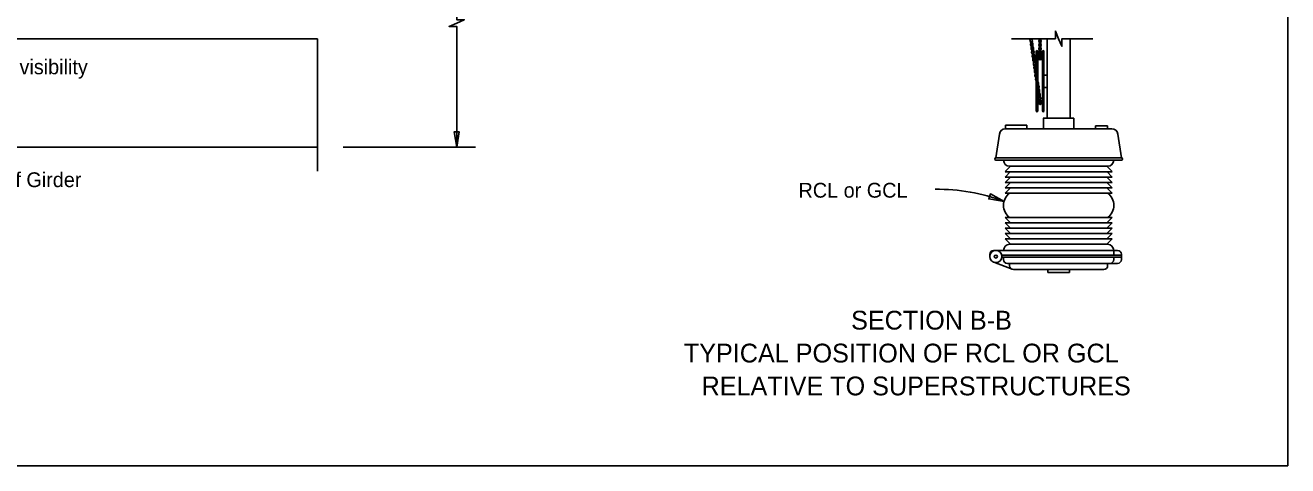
# Model space of a CAD drawing. Extents: x 0 to 20.5, y 0 to 13.
# Drawn here: x 11.94 to 20.53, y 0 to 3 of the extents above; entities that cross this region are included whole.
import ezdxf

# ---------------------------------------------------------------- set-up
doc = ezdxf.new("R2010")
doc.units = 0
for name, color, linetype in [('ActivePts-ConstElements', 7, 'Continuous'), ('Dimension', 7, 'Continuous'), ('Miscellaneous', 7, 'Continuous'), ('Miscellaneous1', 7, 'Continuous'), ('NavLight', 7, 'Continuous'), ('SupstrConc', 7, 'Continuous'), ('TextStructures', 7, 'Continuous')]:
    doc.layers.add(name, color=color, linetype=linetype)

msp = doc.modelspace()

# ---------------------------------------------------------------- linework, layer by layer
at = {"layer": 'ActivePts-ConstElements'}
msp.add_lwpolyline([(0, 0), (20.5253, 0), (20.5253, 12.9731), (0, 12.9731)], close=True, dxfattribs=at)
at = {"layer": 'Dimension'}
msp.add_line((14.0993, 2.1697), (14.9992, 2.1697), dxfattribs=at)
for points in [[(14.8718, 2.1697), (14.8718, 2.9926), (14.8202, 2.9926), (14.8718, 3.0151), (14.9235, 3.0376), (14.8718, 3.0376), (14.8718, 4.7665)], [(5.858, 2.9088), (10.1884, 2.9088), (10.1884, 2.9604), (10.2109, 2.9088), (10.2334, 2.8571), (10.2334, 2.9088), (13.9245, 2.9088)], [(18.6451, 2.9088), (18.9443, 2.9088), (18.9443, 2.9605), (18.9668, 2.9088), (18.9893, 2.8572), (18.9893, 2.9088), (19.2004, 2.9088)], [(13.9245, 2.0075), (13.9245, 2.9088)]]:
    msp.add_lwpolyline(points, dxfattribs=at)
for points in [[(14.8718, 2.1697), (14.8895, 2.2738), (14.8542, 2.2738)], [(18.5953, 1.801), (18.5023, 1.8511), (18.491, 1.8177)]]:
    msp.add_lwpolyline(points, close=True, dxfattribs=at)
msp.add_arc((18.1425, 0.5937), 1.2893, 69.44292, 90.68885, dxfattribs=at)
at = {"layer": 'Miscellaneous'}
for p, q in [((18.8149, 2.8221), (18.8149, 2.4156)), ((18.8253, 2.8221), (18.8253, 2.4156)), ((18.8409, 2.8273), (18.8409, 2.7649)), ((18.8565, 2.8221), (18.8565, 2.4156)), ((18.8669, 2.8221), (18.8669, 2.4156)), ((18.8877, 2.6606), (18.8669, 2.6606)), ((18.8877, 2.5772), (18.8669, 2.5772)), ((18.6386, 2.0396), (18.6021, 2.0031)), ((18.6386, 2.0031), (18.6021, 1.9667)), ((18.9668, 2.003), (18.6022, 2.003)), ((18.9667, 2.003), (19.3314, 2.003)), ((19.2949, 2.0396), (19.3313, 2.0031)), ((19.2949, 2.0031), (19.3313, 1.9667)), ((18.6386, 1.9667), (18.6021, 1.9302)), ((18.6386, 1.9302), (18.6021, 1.8938)), ((18.6386, 1.8938), (18.6021, 1.8573)), ((18.9668, 1.9666), (18.6022, 1.9666)), ((18.9668, 1.9301), (18.6022, 1.9301)), ((18.9668, 1.8937), (18.6022, 1.8937)), ((18.9667, 1.9666), (19.3314, 1.9666)), ((18.9667, 1.9301), (19.3314, 1.9301)), ((18.9667, 1.8937), (19.3314, 1.8937)), ((19.2949, 1.9667), (19.3313, 1.9302)), ((19.2949, 1.9302), (19.3313, 1.8938)), ((19.2949, 1.8938), (19.3313, 1.8573)), ((18.9668, 1.8572), (18.6022, 1.8572)), ((18.9667, 1.8572), (19.3314, 1.8572)), ((18.6386, 1.6542), (18.6021, 1.6906)), ((18.6386, 1.6177), (18.6021, 1.6542)), ((18.9668, 1.6905), (18.6022, 1.6905)), ((18.9668, 1.6541), (18.6022, 1.6541)), ((18.9667, 1.6905), (19.3314, 1.6905)), ((18.9667, 1.6541), (19.3314, 1.6541)), ((19.2949, 1.6542), (19.3313, 1.6906)), ((19.2949, 1.6177), (19.3313, 1.6542)), ((18.6386, 1.5813), (18.6021, 1.6177)), ((18.6386, 1.5448), (18.6021, 1.5813)), ((18.9668, 1.6176), (18.6022, 1.6176)), ((18.9668, 1.5812), (18.6022, 1.5812)), ((18.9667, 1.6176), (19.3314, 1.6176)), ((18.9667, 1.5812), (19.3314, 1.5812)), ((19.2949, 1.5813), (19.3313, 1.6177)), ((19.2949, 1.5448), (19.3313, 1.5813)), ((18.6386, 1.5083), (18.6021, 1.5448)), ((18.9668, 1.5447), (18.6022, 1.5447)), ((18.9667, 1.5447), (19.3314, 1.5447)), ((19.2949, 1.5083), (19.3313, 1.5448))]:
    msp.add_line(p, q, dxfattribs=at)
for centre, radius, start, end in [((18.8201, 2.8221), 0.0052, 0.00303, 179.61227), ((18.8409, 2.7805), 0.0156, 180, 359.8848), ((18.8617, 2.8221), 0.0052, 0.38773, 180.00117), ((18.8201, 2.4156), 0.0052, 180.38773, 359.99697), ((18.8409, 2.4572), 0.0156, 0.1152, 180), ((18.8617, 2.4156), 0.0052, 179.99883, 359.61227), ((18.6958, 1.774), 0.1041, 126.81262, 233.18738), ((19.2377, 1.774), 0.1041, 306.81262, 53.18738)]:
    msp.add_arc(centre, radius, start, end, dxfattribs=at)
for centre, major_axis, ratio, start_param, end_param in [((18.7799, 2.8958), (-0.0022, 0.0152), 0.530594, 0.467517, 5.663262), ((18.7799, 2.8958), (-0.0019, 0.0131), 0.458548, 0.090049, 6.06136), ((18.7761, 2.9221), (-0.0022, 0.0152), 0.530594, 2.556023, 3.574757), ((18.8399, 2.9192), (-0.0001, 0.0153), 0.530594, 2.31426, 3.960984), ((18.8399, 2.9192), (-0.0001, 0.0133), 0.458548, 2.4686, 3.807723), ((18.8411, 2.7598), (-0.0001, 0.0153), 0.530594, 5.178718, 7.393601), ((18.8411, 2.7598), (-0.0001, 0.0133), 0.458548, 5.185958, 7.38546)]:
    msp.add_ellipse(centre, major_axis=major_axis, ratio=ratio, start_param=start_param, end_param=end_param, dxfattribs=at)
for centre, major_axis, ratio in [((18.7837, 2.8695), (-0.0022, 0.0152), 0.530594), ((18.7837, 2.8695), (-0.0019, 0.0131), 0.458548), ((18.7874, 2.8432), (-0.0022, 0.0152), 0.530594), ((18.7874, 2.8432), (-0.0019, 0.0131), 0.458548), ((18.8401, 2.8927), (-0.0001, 0.0153), 0.530594), ((18.8403, 2.8661), (-0.0001, 0.0153), 0.530594), ((18.8405, 2.8395), (-0.0001, 0.0153), 0.530594), ((18.8401, 2.8927), (-0.0001, 0.0133), 0.458548), ((18.8403, 2.8661), (-0.0001, 0.0133), 0.458548), ((18.8405, 2.8395), (-0.0001, 0.0133), 0.458548), ((18.7912, 2.8169), (-0.0022, 0.0152), 0.530594), ((18.7912, 2.8169), (-0.0019, 0.0131), 0.458548), ((18.795, 2.7906), (-0.0022, 0.0152), 0.530594), ((18.795, 2.7906), (-0.0019, 0.0131), 0.458548), ((18.7988, 2.7643), (-0.0022, 0.0152), 0.530594), ((18.7988, 2.7643), (-0.0019, 0.0131), 0.458548), ((18.8026, 2.738), (-0.0022, 0.0152), 0.530594), ((18.8026, 2.738), (-0.0019, 0.0131), 0.458548), ((18.8407, 2.813), (-0.0001, 0.0153), 0.530594), ((18.8409, 2.7864), (-0.0001, 0.0153), 0.530594), ((18.8407, 2.813), (-0.0001, 0.0133), 0.458548), ((18.8409, 2.7864), (-0.0001, 0.0133), 0.458548), ((18.8064, 2.7117), (-0.0022, 0.0152), 0.530594), ((18.8064, 2.7117), (-0.0019, 0.0131), 0.458548), ((18.8101, 2.6854), (-0.0022, 0.0152), 0.530594), ((18.8101, 2.6854), (-0.0019, 0.0131), 0.458548), ((18.8139, 2.6591), (-0.0022, 0.0152), 0.530594), ((18.8139, 2.6591), (-0.0019, 0.0131), 0.458548), ((18.8177, 2.6328), (-0.0022, 0.0152), 0.530594), ((18.8177, 2.6328), (-0.0019, 0.0131), 0.458548), ((18.8215, 2.6066), (-0.0022, 0.0152), 0.530594), ((18.8215, 2.6066), (-0.0019, 0.0131), 0.458548), ((18.8253, 2.5803), (-0.0022, 0.0152), 0.530594), ((18.8253, 2.5803), (-0.0019, 0.0131), 0.458548), ((18.8291, 2.554), (-0.0022, 0.0152), 0.530594), ((18.8291, 2.554), (-0.0019, 0.0131), 0.458548), ((18.8328, 2.5277), (-0.0022, 0.0152), 0.530594), ((18.8328, 2.5277), (-0.0019, 0.0131), 0.458548), ((18.8366, 2.5014), (-0.0022, 0.0152), 0.530594), ((18.8366, 2.5014), (-0.0019, 0.0131), 0.458548), ((18.8404, 2.4751), (-0.0022, 0.0152), 0.530594), ((18.8404, 2.4751), (-0.0019, 0.0131), 0.458548)]:
    msp.add_ellipse(centre, major_axis=major_axis, ratio=ratio, dxfattribs=at)
at = {"layer": 'Miscellaneous1'}
msp.add_lwpolyline([(0, 12.9731), (20.5253, 12.9731), (20.5253, 0), (0, 0)], close=True, dxfattribs=at)
at = {"layer": 'NavLight'}
for p, q in [((18.8877, 2.9088), (18.8877, 2.3677)), ((19.046, 2.9088), (19.046, 2.3677)), ((18.6048, 2.3208), (18.6048, 2.2948)), ((18.7506, 2.3208), (18.6048, 2.3208)), ((18.7506, 2.3208), (18.7506, 2.2948)), ((19.071, 2.3677), (18.8625, 2.3677)), ((18.8626, 2.3676), (18.8626, 2.2948)), ((19.071, 2.3676), (19.071, 2.2948)), ((18.5395, 2.097), (18.5635, 2.2593)), ((18.9668, 2.2948), (18.6048, 2.2948)), ((18.9668, 2.2948), (19.3287, 2.2948)), ((19.2168, 2.3156), (19.3, 2.3156)), ((19.2168, 2.3156), (19.2168, 2.2948)), ((19.3, 2.3156), (19.3, 2.2948)), ((19.3938, 2.097), (19.3698, 2.2593)), ((18.9667, 2.0969), (18.5395, 2.0969)), ((18.9667, 2.0813), (18.5395, 2.0813)), ((18.9667, 2.0969), (19.3939, 2.0969)), ((18.9667, 2.0813), (19.3939, 2.0813)), ((18.9667, 2.0396), (18.6334, 2.0396)), ((18.9668, 2.0396), (19.3, 2.0396)), ((18.9668, 1.4666), (18.5239, 1.4666)), ((18.9667, 1.5083), (18.6334, 1.5083)), ((18.9668, 1.5083), (19.3, 1.5083)), ((18.9668, 1.4666), (19.3678, 1.4666)), ((19.3418, 1.4354), (19.3418, 1.4666)), ((18.4979, 1.4406), (18.4979, 1.425)), ((18.6502, 1.3381), (18.5247, 1.3861)), ((18.9668, 1.4353), (18.58, 1.4353)), ((18.9668, 1.4197), (18.581, 1.4197)), ((18.5918, 1.4198), (18.5918, 1.4041)), ((18.9668, 1.3781), (18.6178, 1.3781)), ((18.6335, 1.3781), (18.6335, 1.3624)), ((18.9668, 1.4353), (19.3939, 1.4353)), ((18.9668, 1.4197), (19.3939, 1.4197)), ((18.9668, 1.3781), (19.3678, 1.3781)), ((19.3, 1.3781), (19.3, 1.3624)), ((19.3418, 1.4198), (19.3418, 1.4041)), ((19.3938, 1.4406), (19.3938, 1.4041)), ((18.9668, 1.3364), (18.6595, 1.3364)), ((18.8939, 1.3155), (18.8939, 1.3363)), ((18.9668, 1.3155), (18.8939, 1.3155)), ((18.9668, 1.3364), (19.274, 1.3364)), ((18.9668, 1.3155), (19.0397, 1.3155)), ((19.0397, 1.3155), (19.0397, 1.3363))]:
    msp.add_line(p, q, dxfattribs=at)
for radius in [0.0416, 0.0104]:
    msp.add_circle((18.5396, 1.425), radius, dxfattribs=at)
for centre, radius, start, end in [((18.6048, 2.2532), 0.0417, 90, 171.57567), ((19.3285, 2.2532), 0.0417, 8.42433, 90), ((18.5395, 2.0891), 0.00781, 90, 270), ((18.6334, 2.0813), 0.0417, 180, 270), ((19.3001, 2.0813), 0.0417, 270, 360), ((19.3939, 2.0891), 0.00781, 270, 90), ((18.5239, 1.4406), 0.026, 90, 180), ((18.6334, 1.4666), 0.0417, 90, 180), ((19.3001, 1.4666), 0.0417, 0, 90), ((19.3678, 1.4406), 0.026, 0, 90), ((18.6178, 1.4041), 0.026, 180, 270), ((19.3158, 1.4041), 0.026, 270, 0), ((19.3678, 1.4041), 0.026, 270.00345, 360), ((18.6595, 1.3624), 0.026, 180, 270), ((19.274, 1.3624), 0.026, 270, 0)]:
    msp.add_arc(centre, radius, start, end, dxfattribs=at)
at = {"layer": 'SupstrConc'}
msp.add_line((8.5792, 2.1697), (13.9245, 2.1697), dxfattribs=at)

# ---------------------------------------------------------------- texts
at = {"layer": 'Dimension'}
for s, height, p in [('Install Light Fixture so as to ensure visibility ', 0.1008, (9.7699, 2.6664)), ('SECTION B-B', 0.128, (17.5549, 0.9276)), ('TYPICAL POSITION OF RCL OR GCL', 0.128, (16.4172, 0.7036)), ('RELATIVE TO SUPERSTRUCTURES', 0.128, (16.5377, 0.4796))]:
    msp.add_text(s, height=height, dxfattribs=at).set_placement(p)
at = {"layer": 'TextStructures'}
for s, p in [('Bottom of Girder', (11.33, 1.8977)), ('RCL or GCL', (17.197, 1.8261))]:
    msp.add_text(s, height=0.1008, dxfattribs=at).set_placement(p)

doc.saveas('drawing.dxf')
